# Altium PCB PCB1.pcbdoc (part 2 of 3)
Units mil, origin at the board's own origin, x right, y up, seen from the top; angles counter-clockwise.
Board outline 5971.11 x 4241.46 mil, 4 copper layers (Top Layer, Inner1, Inner2, Bottom Layer); 197 components, 112 nets, 603 pads, 396 vias.
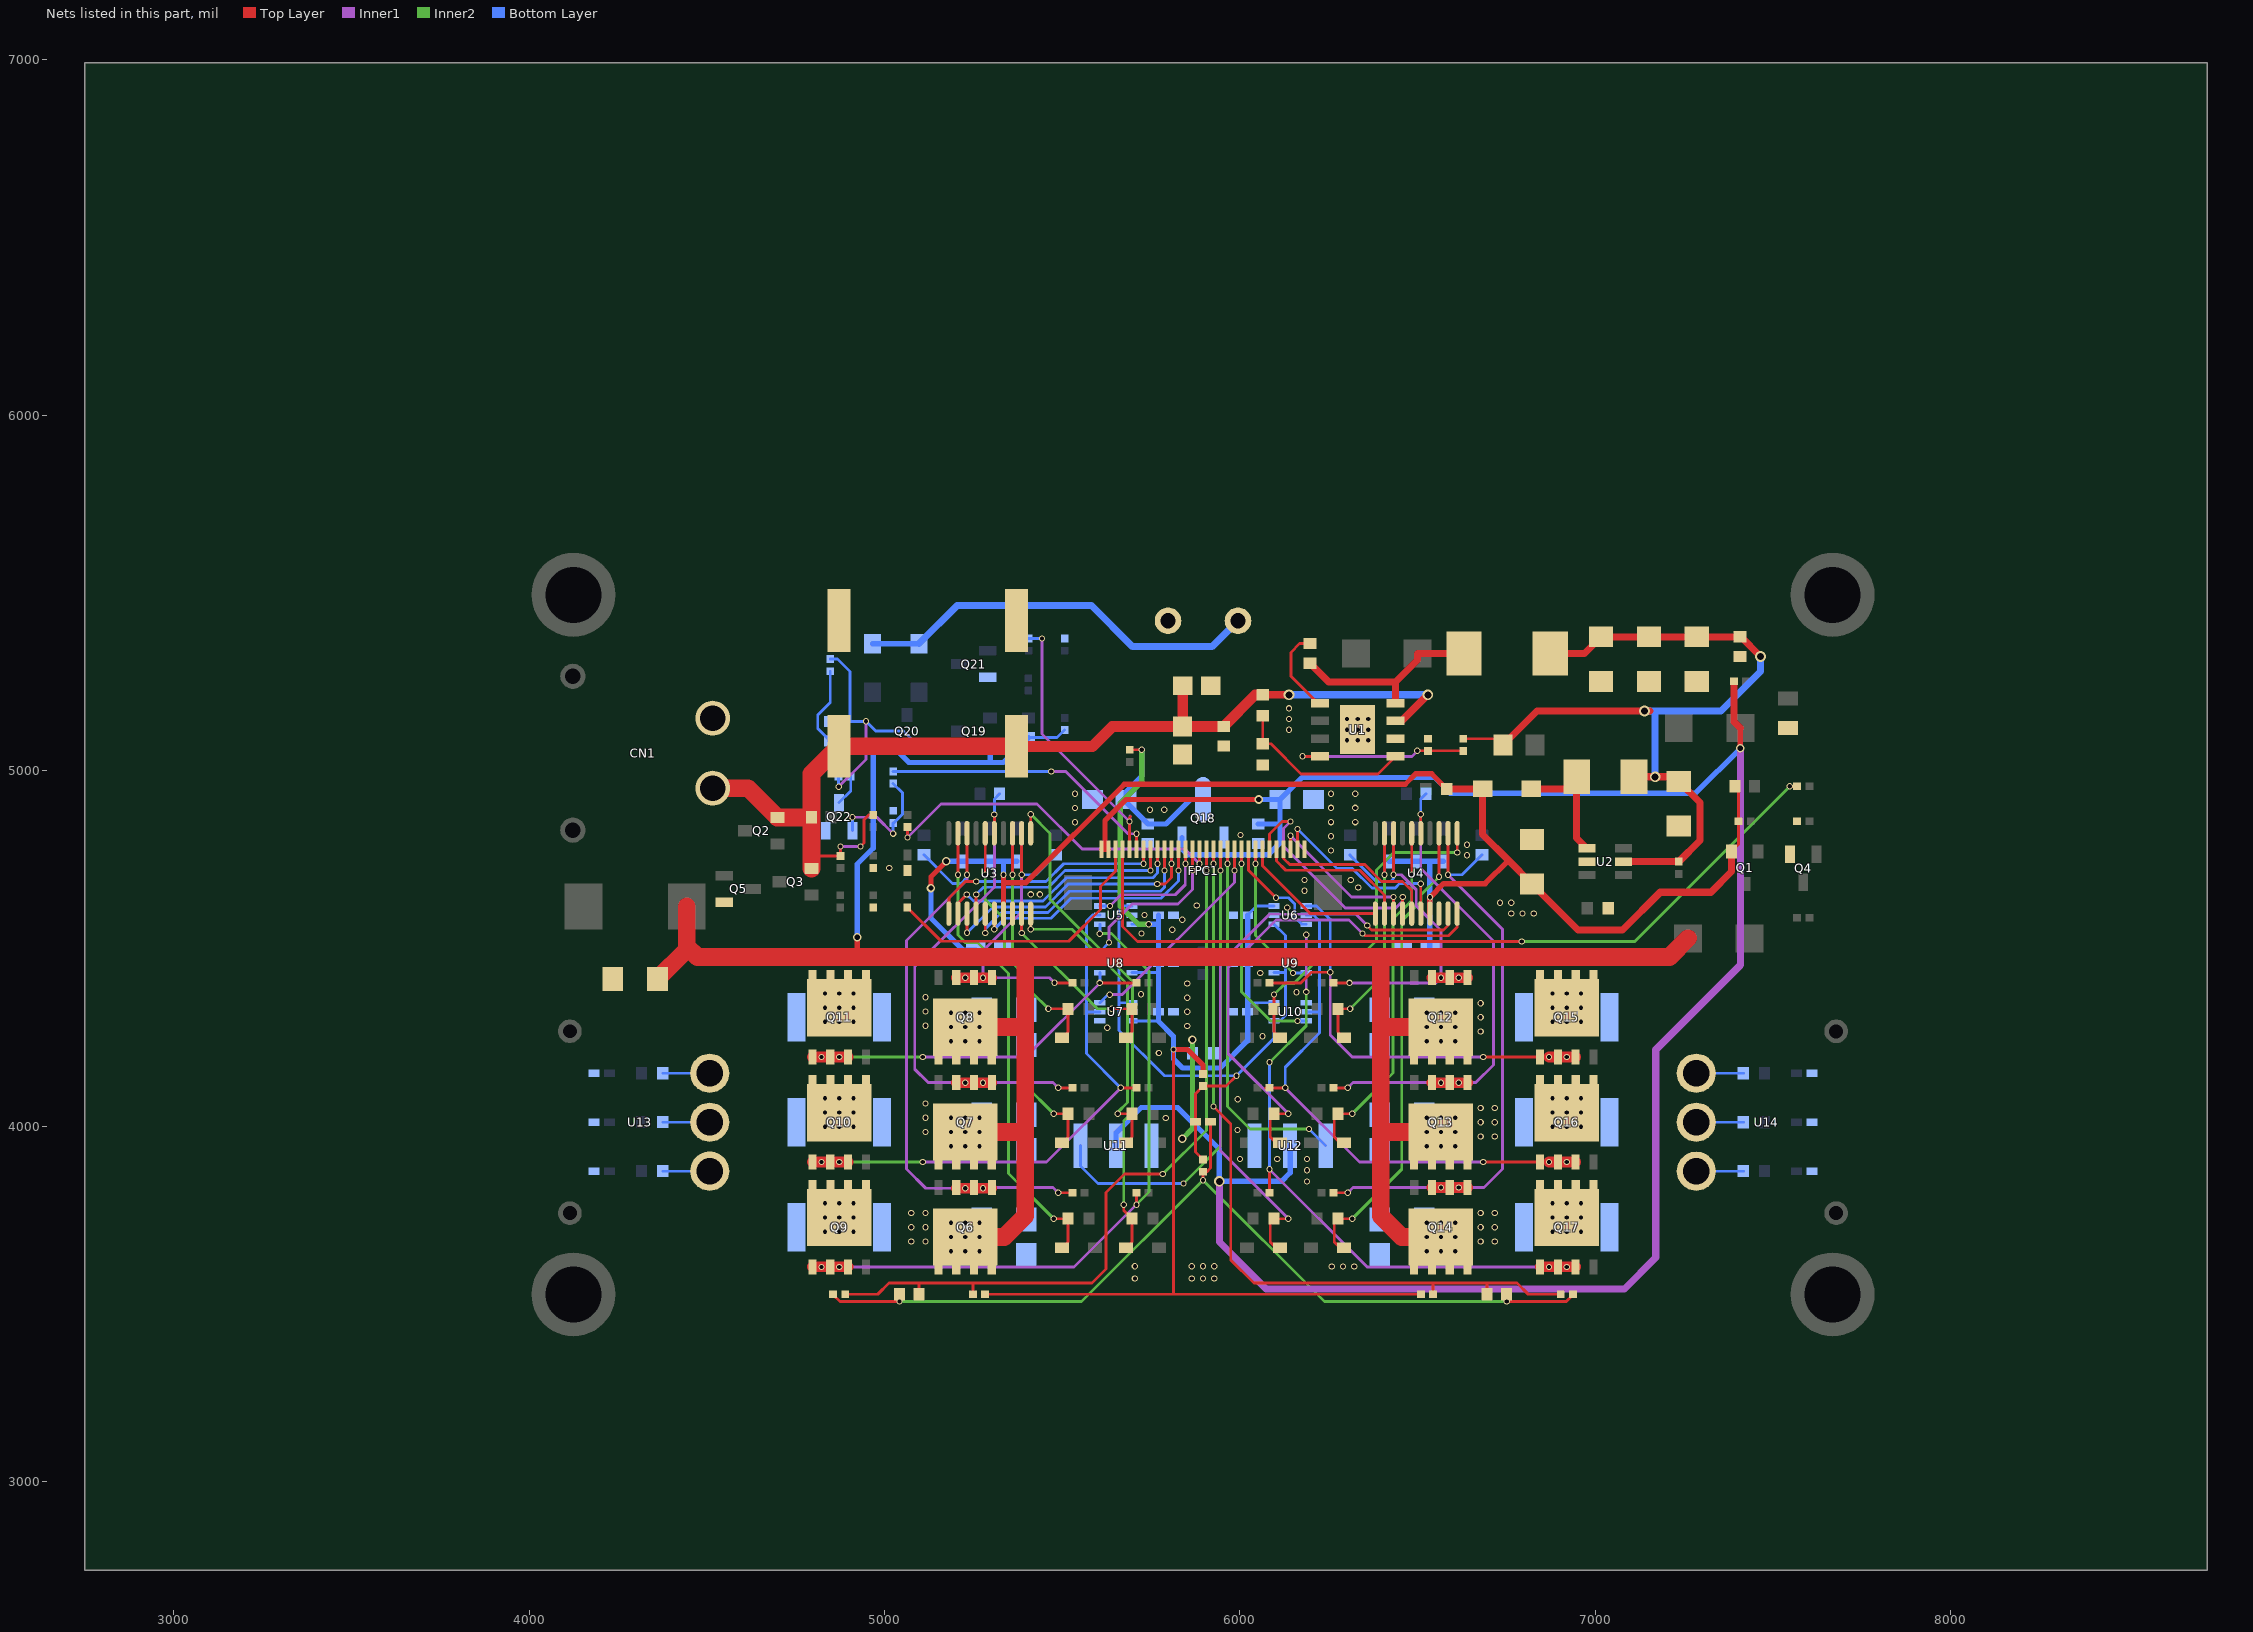
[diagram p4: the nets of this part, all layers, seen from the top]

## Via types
v1: diameter 17.7, hole 12, Top Layer to Bottom Layer, 383 vias
v2: diameter 24, hole 15, Top Layer to Bottom Layer, 7 vias
v3: diameter 30, hole 19.7, Top Layer to Bottom Layer, 6 vias

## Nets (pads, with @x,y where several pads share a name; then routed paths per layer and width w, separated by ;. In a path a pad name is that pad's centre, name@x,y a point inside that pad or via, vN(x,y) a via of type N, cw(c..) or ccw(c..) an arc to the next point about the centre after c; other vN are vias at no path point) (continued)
$1N126462: Q22.1 R78.1 R79.1 | length 334.5
  Inner1 w8: v1(4909.41,4868.96) 4978.03,4868.96 v1(5024.01,4822.99)
  Bottom Layer w8: Q22.1@4909.41,4831.59 v1(4909.41,4868.96) ; v1(5024.01,4822.99) R79.1@5024.01,4853.23 5025.83,4853.23 5049.98,4877.38 5049.98,4937.95 R78.1@5024.01,4963.92
$1N126467: C61.1 Q20.1 R73.1 R75.2 | length 738.7
  Inner1 w8: v1(4870.79,4954.77) 4947.98,5031.96 v1(4947.98,5138.96)
  Bottom Layer w8: C61.1@4847.11,5138.52 4902.68,5138.52 ; R73.1@4847.11,5314 4867.94,5314 4902.68,5279.26 4902.68,5138.52 ; v1(4870.79,4954.77) R75.2@4870.79,4982.68 ; Q20.1@5100.5,5065.69 5099.26,5065.69 5052.98,5111.96 4974.98,5111.96 v1(4947.98,5138.96) 4947.54,5138.52 4902.68,5138.52
$1N126474: Q22.3 R75.1 | length 86
  Bottom Layer w8: Q22.3@4872.01,4910.33 4904.87,4943.19 R75.1@4904.87,4982.68
$1N126564: D24.1 D25.1 U15.1 | length 1151.1
  Bottom Layer w15: D25.1@4966.01,5357.58 D24.1@5097.01,5357.58
  Bottom Layer w20: D24.1@5097.01,5357.58 5204.39,5464.96 5581.98,5464.96 5697.98,5348.96 5921.53,5348.96 U15.1@5994.43,5421.87
$1N167795: R2.1 R9.2 U1.5 | length 507.7
  Top Layer w8: R2.1@6064.01,5154.24 R9.2@6064.01,5075.62 6087.27,5075.62 6171.88,4991.01 6388.24,4991.01 U1.5@6437.56,5040.34
$1N168255: C3.1 U1.1 | length 244.2
  Top Layer w8: C3.1@6197.01,5357.52 6167.64,5357.52 6143.18,5333.06 6143.18,5265.96 6218.81,5190.34 U1.1@6224.97,5190.34
$1N168264: C3.2 L1.1 U1.8 | length 558.4
  Top Layer w20: C3.2@6197.01,5302.4 6249.8,5249.61 6437.56,5249.61 ; U1.8@6437.56,5190.34 6437.56,5249.61 ; L1.1@6630.31,5329.96 6499.62,5329.96 6499.62,5311.67 6437.56,5249.61
$1N168458: R3.1 R10.2 U1.4 | length 507.8
  Top Layer w8: v1(6175.98,5040.34) U1.4@6224.97,5040.34 ; v1(6499.02,5055.92) R10.2@6529.01,5055.92 R3.1@6627.82,5055.92
  Inner1 w8: v1(6175.98,5040.34) 6484.35,5040.34 6499.02,5055 v1(6499.02,5055.92)
$1N213205: D2.2 L2.2 U2.1 | length 355.9
  Top Layer w20: D2.2@6819.32,4948.96 6913.3,4948.96 L2.2@6947.3,4982.96 6947.3,4810.88 U2.1@6976.81,4781.36
+3.3V: C47.2 C48.2 C49.2 C53.2 C54.2 C55.2 C58.1 C59.2 Q18.2 R64.2 R65.2 R66.1 R71.2 U5.3 U6.3 U7.3 U8.3 U9.3 U10.3 | length 4559.5
  Top Layer w8: R64.2@5283.12,3526.84 5812.88,3526.84 ; R71.2@5690.01,5059 v1(5723.84,5059) ; v1(5812.88,4215.76) 5812.88,3526.84 ; R65.2@6508.84,3526.84 5812.88,3526.84
  Top Layer w15: v1(5812.88,4215.76) 5852.18,4215.76 5895.98,4171.96 R66.1@5895.98,4146.7
  Inner2 w15: v1(5723.84,5059) 5723.84,4969.12 5663.48,4908.76 5663.48,4618.36 5713.7,4568.14 v1(5743.13,4568.14)
  Bottom Layer w8: U7.3@5696.28,4295.91 5769.58,4295.91 ; U8.3@5696.28,4432.02 5770.52,4432.02 ; U5.3@5696.28,4568.14 v1(5743.13,4568.14) ; 5770.15,4568.14 5770.52,4568.51 ; 6021.44,4347.11 U10.3@6095.68,4347.11 ; 6021.44,4483.23 U9.3@6095.68,4483.23 ; C55.2@6021.44,4593.76 6047.02,4619.34 U6.3@6095.68,4619.34
  Bottom Layer w15: v1(5723.84,5059) 5723.84,4984.92 5679.22,4940.3 C58.1@5679.22,4918.96 5679.22,4911.78 C59.2@5740.98,4850.02 5792.04,4850.02 5860.98,4918.96 Q18.2@5896.01,4918.96 ; v1(5743.13,4568.14) 5770.15,4568.14 ; C49.2@5770.52,4593.76 5770.52,4568.51 C48.2@5770.52,4457.66 5770.52,4432.02 C47.2@5770.52,4321.46 5770.52,4294.97 5812.88,4252.61 v1(5812.88,4215.76) 5812.88,4188.86 5838.08,4163.66 5944.58,4163.66 6021.44,4240.52 C53.2@6021.44,4321.46 6021.44,4347.11 C54.2@6021.44,4457.66 6021.44,4483.23 C55.2@6021.44,4593.76
+5.8V: C5.2 C6.2 C7.2 C8.2 C9.1 F1.1 L1.2 L2.1 R3.2 R11.2 U2.5 | length 2368.1
  Top Layer w8: R3.2@6627.82,5090 6721.96,5090 F1.1@6740,5071.96
  Top Layer w20: F1.1@6740,5071.96 6836,5167.96 v3@7152.98,5167.96 ; L1.2@6872.71,5329.96 6969.31,5329.96 C6.2@7016.01,5376.66 C7.2@7150.69,5376.66 C8.2@7285.38,5376.66 C9.1@7407.01,5376.66 7409.66,5376.66 v3(7464.78,5321.54) ; U2.5@7079.17,4743.96 R11.2@7234.57,4743.98 ; L2.1@7108.72,4982.96 v3(7168.21,4982.96) 7221.26,4982.96 C5.2@7234.57,4969.66 7293.98,4910.25 7293.98,4803.4 R11.2@7234.57,4743.98
  Bottom Layer w20: v3(7138.21,5167.96) 7168.21,5167.96 ; v3(7168.21,4982.96) 7168.21,5167.96 ; v3(7464.78,5321.54) 7464.78,5279.54 7353.21,5167.96 7168.21,5167.96
+5V: C56.1 C57.2 FPC1.1 FPC1.2 Q18.3 R70.2 U11.2 U12.2 | length 6520.5
  Top Layer w15: FPC1.1@5610.55,4778.4 5620.12,4778.4 ; FPC1.2@5630.23,4778.4 5620.12,4778.4 ; v2(6053.18,4918.96) 5678.98,4918.96 5620.12,4860.1 5620.12,4778.4 ; v2(7407.78,5062.96) 7407.79,5119.96
  Top Layer w20: R70.2@7389.97,5251.26 7389.97,5137.78 7407.79,5119.96
  Inner1 w20: v3(5941.98,3844.46) 5941.98,3673.96 6073.98,3541.96 7081.98,3541.96 7169.98,3629.96 7169.98,4214.96 7407.78,4452.76 v2(7407.78,5062.96)
  Bottom Layer w15: U11.2@5650.98,3944.96 5650.98,3980.96 5722.23,4052.21 5824.73,4052.21 5941.98,3934.96 v3(5941.98,3844.46) 6116.78,3844.46 6140.98,3868.66 U12.2@6140.98,3944.96 ; Q18.3@5836.95,4812.17 5836.95,4778.92 5851.95,4763.92 6080.66,4763.92 6112.74,4796.01 6112.74,4850.02 ; C57.2@6050.98,4850.02 6112.74,4850.02 ; v2(6053.18,4918.96) C56.1@6112.74,4918.96 ; v2(7407.78,5062.96) 7281.78,4936.96 6591.98,4936.96 6547.98,4980.96 6174.74,4980.96 C56.1@6112.74,4918.96 ; 6112.74,4850.02 C56.1@6112.74,4918.96
+12V: C13.2 C14.2 C31.2 C46.2 D2.1 D6.2 D7.2 D8.2 D15.2 D16.2 D17.2 Q1.2 R4.2 R6.2 U3.7 U4.7 | length 4152.9
  Top Layer w8: Q1.2@7382.82,4771.99 7403.19,4792.35 R6.2@7403.19,4857.68 7403.19,4946.12 C14.2@7392.67,4956.63
  Top Layer w15: v2(5130.38,4669.76) 5130.38,4701.63 v2(5173.55,4744.8) ; U3.7@5334.4,4597.93 5334.39,4685.01 ; v1(5334.39,4707.36) 5334.39,4685.01 ; U4.7@6534.4,4597.93 v1(6534.39,4643.6) 6572.86,4682.06 6689.68,4682.06 6755.43,4747.81 ; R4.2@6581.64,4948.96 6539.64,4990.96 6493.98,4990.96 6464.98,4961.96 5674.59,4961.96 5397.64,4685.01 5334.39,4685.01
  Top Layer w20: R4.2@6581.64,4948.96 D2.1@6682.7,4948.96 ; D2.1@6682.7,4945.95 6682.7,4820.55 6755.43,4747.81 C13.2@6821.98,4681.26 6951.18,4552.06 7076.58,4552.06 7182.58,4658.06 7324.93,4658.06 7382.82,4715.95 Q1.2@7382.82,4771.99
  Top Layer w30: D2.1@6682.7,4945.95 D2.1@6682.7,4948.96
  Bottom Layer w15: v2(5130.38,4669.76) 5130.38,4584.86 5220.28,4494.96 C31.2@5256.61,4494.96 ; v2(5173.55,4744.8) D8.2@5220.01,4744.8 D7.2@5295.98,4744.8 5334.39,4744.8 ; v1(5334.39,4707.36) 5334.39,4744.8 ; D6.2@5372.01,4744.8 5334.39,4744.8 ; D17.2@6419.98,4744.8 D16.2@6495.98,4744.8 6535.98,4744.8 ; C46.2@6535.35,4494.96 6534.39,4495.92 v1(6534.39,4643.6) 6534.39,4743.21 6535.98,4744.8 ; D15.2@6571.98,4744.8 6535.98,4744.8
DGND: C47.1 C48.1 C49.1 C50.1 C51.1 C52.1 C53.1 C54.1 C55.1 C56.2 C57.1 C58.2 C59.1 FPC1.30 Q18.1 R15.1 R67.2 R68.1 R69.1 U5.2 U6.2 U7.2 U8.2 U9.2 U10.2 | length 2604.2
  Top Layer w8: R68.1@4855.34,3526.84 4855.34,3525.01 4874.15,3506.21 v1(5041.69,3506.21) C50.1@5041.69,3526.84 ; v1(5895.98,3847.66) R67.2@5895.98,3871.62 5907.3,3871.62 5917.44,3881.77 C52.1@5917.44,4011.66 ; v1(6750.27,3506.21) 6917.82,3506.21 6936.62,3525.01 R69.1@6936.62,3526.84 ; v1(6750.27,3506.21) C51.1@6750.29,3526.86
  Inner2 w8: v1(5041.69,3506.21) 5554.53,3506.21 v1(5895.98,3847.66) 6237.44,3506.21 v1(6750.27,3506.21)
  other v1: 5790.98,4022.96 5993.38,4075.26 5771.83,4205.92 6063.37,4252.81 5851.98,4281.46 5851.98,4321.46 5851.98,4361.46 5721.65,4370.63 5851.98,4401.46 6057.35,4431.02 5722.98,4541.96 5809.41,4552.39 5837.7,4580.68 5731.28,4593.74 6132.87,4614.76 5877.98,4620.96 6255.98,4775.35 6255.98,4815.35 6001.65,4818.86 5535.98,4854.96 6255.98,4855.35 5746.98,4890.06 5786.98,4890.06 5535.98,4894.96 6255.98,4895.35 5535.98,4934.96 6255.98,4935.35
M0_ADC: FPC1.20 U7.6 | length 611.7
  Top Layer w8: v1(5984.56,4718.96) FPC1.20@5984.56,4778.4
  Inner1 w8: v1(5633.53,4369.86) 5668.54,4369.86 5984.56,4685.89 v1(5984.56,4718.96)
  Bottom Layer w8: U7.6@5605.68,4347.11 5628.44,4369.86 v1(5633.53,4369.86)
M0_ADC_A: FPC1.13 U5.6 | length 364.6
  Top Layer w8: v1(5846.77,4737.96) FPC1.13@5846.77,4778.4
  Inner1 w8: v1(5633.98,4619.34) 5665.6,4650.96 5817.78,4650.96 5845.93,4679.11 5845.93,4737.12 v1(5846.77,4737.96)
  Bottom Layer w8: U5.6@5605.68,4619.34 v1(5633.98,4619.34)
M0_ADC_C: FPC1.14 U8.6 | length 478.5
  Top Layer w8: v1(5866.45,4718.96) FPC1.14@5866.45,4778.4
  Inner1 w8: v1(5631.68,4516.32) 5631.68,4559.56 5696.98,4624.86 5825.48,4624.86 5866.45,4665.83 v1(5866.45,4718.96)
  Bottom Layer w8: U8.6@5605.68,4483.23 5605.68,4490.32 v1(5631.68,4516.32)
M0_BK_OUT: FPC1.5 R76.2 | length 764.7
  Top Layer w8: FPC1.5@5689.29,4778.4 v1(5689.28,4857.16) 5689.28,4868.37 5692.17,4871.26
  Inner1 w8: v1(5442.98,5372.23) 5442.98,5103.46 v1(5689.28,4857.16) 5690.73,4858.61 5690.73,4872.71
  Bottom Layer w8: R76.2@5405.57,5372.23 v1(5442.98,5372.23)
M0_HA: D9.1 R20.1 U3.19 | length 1345
  Top Layer w8: v1(5206.44,4707.36) U3.19@5206.44,4823.99 ; v1(5475.91,3739.49) R20.1@5516.01,3739.49 5516.01,3673.97 D9.1@5499.5,3657.46
  Inner2 w8: v1(5206.44,4707.36) 5206.44,4537.51 5226.98,4516.96 5260.98,4516.96 5348.98,4428.96 5348.98,3866.42 v1(5475.91,3739.49)
M0_HB: D10.1 R21.1 U3.16 | length 998.1
  Top Layer w8: v1(5283.21,4707.36) U3.16@5283.22,4823.99 ; v1(5475.91,4034.69) R21.1@5516.01,4034.69 5516.01,3969.17 D10.1@5499.5,3952.66
  Inner2 w8: v1(5283.21,4707.36) 5283.21,4636.73 5336.98,4582.96 5336.98,4481.96 5393.98,4424.96 5393.98,4116.62 v1(5475.91,4034.69)
M0_HC: D11.1 R22.1 U3.13 | length 679.8
  Top Layer w8: v1(5359.98,4707.36) U3.13@5359.99,4823.99 ; v1(5460.91,4329.99) R22.1@5516.01,4329.99 5516.01,4264.47 D11.1@5499.5,4247.96
  Inner2 w8: v1(5359.98,4707.36) 5359.98,4489.96 5415.98,4433.96 5415.98,4374.92 v1(5460.91,4329.99)
M0_ISENSOR_NA: Q10.1 Q10.2 Q10.3 R34.1 R36.1 R37.1 R41.2 U5.5 U7.5 U8.5 | length 1651.9
  Top Layer w8: v1(5664.48,4107.66) R36.1@5708.63,4107.66
  Top Layer w30: Q10.1@4797.26,3899.11 v1(4822.26,3899.07) Q10.2@4847.26,3899.11 v1(4872.46,3899.07) Q10.3@4897.26,3899.11
  Inner1 w8: v1(5107.28,3899.07) 5455.89,3899.07 v1(5664.48,4107.66)
  Inner2 w8: v1(4872.46,3899.07) v1(5107.28,3899.07)
  Bottom Layer w8: U7.5@5605.68,4321.51 5567.98,4321.51 ; U8.5@5605.68,4457.62 5567.98,4457.62 ; U5.5@5605.68,4593.74 5584.76,4593.74 5567.98,4576.96 5567.98,4457.62 ; v1(5664.48,4107.66) 5567.98,4204.16 5567.98,4321.51 ; 5567.98,4321.51 5567.98,4457.62
M0_ISENSOR_PA: Q9.1 Q9.2 Q9.3 R34.2 R35.1 U5.4 | length 1922.6
  Top Layer w8: v1(5708.58,3779.06) R35.1@5708.63,3812.46
  Top Layer w30: Q9.1@4797.26,3603.86 4822.26,3603.86 Q9.2@4847.26,3603.86 4872.46,3603.86 Q9.3@4897.26,3603.86
  Inner1 w8: v1(4872.46,3603.82) 5533.34,3603.82 v1(5708.58,3779.06)
  Inner2 w8: v1(5605.68,4541.56) 5638.38,4541.56 5744.38,4435.56 5744.38,3814.86 v1(5708.58,3779.06)
  Bottom Layer w8: v1(5605.68,4541.56) U5.4@5605.68,4568.14
  other v1: 4822.26,3603.82
M0_ISENSOR_PC: Q11.1 Q11.2 Q11.3 R37.2 R38.1 U8.4 | length 1051.6
  Top Layer w8: v1(5605.68,4402.96) R38.1@5708.63,4402.96
  Top Layer w30: Q11.1@4797.26,4194.36 4822.26,4194.36 Q11.2@4847.26,4194.36 4872.46,4194.36 Q11.3@4897.26,4194.36
  Inner1 w8: v1(5107.28,4194.32) 5397.05,4194.32 v1(5605.68,4402.96)
  Inner2 w8: v1(4872.46,4194.32) v1(5107.28,4194.32)
  Bottom Layer w8: v1(5605.68,4402.96) U8.4@5605.68,4432.02
  other v1: 4822.26,4194.32
M0_LA: D12.1 R30.1 U3.11 | length 1419.2
  Top Layer w8: U3.11@5411.17,4823.99 v1(5411.17,4877.8) ; v1(5672.91,3779.06) 5672.91,3762.59 R30.1@5696.01,3739.49 5696.01,3673.97 D12.1@5679.5,3657.46
  Inner2 w8: v1(5411.17,4877.8) 5465.84,4823.13 5465.84,4638.31 5697.28,4406.86 5697.28,4038.26 5672.91,4013.89 v1(5672.91,3779.06)
M0_LB: D13.1 R31.1 U3.10 | length 884.6
  Top Layer w8: v1(5411.17,4554.09) U3.10@5411.17,4597.93 ; v1(5655.91,4034.69) R31.1@5696.01,4034.69 5696.01,3969.17 D13.1@5679.5,3952.66
  Inner2 w8: v1(5411.17,4554.09) 5527.75,4554.09 5683.33,4398.51 5683.33,4066.31 5655.91,4038.89 v1(5655.91,4034.69)
M0_LC: D14.1 R33.1 U3.9 | length 542.4
  Top Layer w8: v1(5385.58,4543.09) U3.9@5385.58,4597.93 ; v1(5638.91,4329.99) R33.1@5696.01,4329.99 5696.01,4264.47 D14.1@5679.5,4247.96
  Inner2 w8: v1(5385.58,4543.09) 5598.68,4329.99 v1(5638.91,4329.99)
M0_TIM1_CH1: FPC1.11 U3.3 | length 772.5
  Top Layer w8: v1(5232.03,4544.12) U3.3@5232.03,4597.93 ; v1(5766.98,4680.96) 5788.98,4680.96 5807.4,4699.38 v1(5807.4,4737.96) FPC1.11@5807.4,4778.4
  Bottom Layer w8: v1(5232.03,4544.12) 5304.8,4616.89 5452.54,4616.89 5516.61,4680.96 v1(5766.98,4680.96)
M0_TIM1_CH1N: FPC1.12 U3.6 | length 706.8
  Top Layer w8: v1(5308.78,4554.09) U3.6@5308.81,4597.93 ; v1(5827.08,4718.96) FPC1.12@5827.08,4778.4
  Bottom Layer w8: v1(5308.78,4554.09) 5339.58,4584.89 5468.54,4584.89 5524.61,4640.96 5777.98,4640.96 5827.08,4690.06 v1(5827.08,4718.96)
M0_TIM1_CH2: FPC1.9 U3.2 | length 708
  Top Layer w8: U3.2@5206.44,4597.93 5206.44,4627.2 v1(5230.98,4651.74) ; v1(5768.03,4737.96) FPC1.9@5768.03,4778.4
  Bottom Layer w8: v1(5230.98,4651.74) 5249.83,4632.89 5445.91,4632.89 5511.98,4698.96 5755,4698.96 5768.03,4711.99 v1(5768.03,4737.96)
M0_TIM1_CH2N: FPC1.10 U3.5 | length 726.1
  Top Layer w8: v1(5283.22,4543.12) U3.5@5283.22,4597.93 ; v1(5787.71,4718.96) FPC1.10@5787.71,4778.4
  Bottom Layer w8: v1(5283.22,4543.12) 5283.22,4555.2 5328.91,4600.89 5459.91,4600.89 5519.98,4660.96 5776.56,4660.96 5787.71,4672.11 v1(5787.71,4718.96)
M0_TIM1_CH3: FPC1.7 U3.1 | length 672
  Top Layer w8: U3.1@5180.85,4597.93 5180.85,4641.83 5227.06,4688.04 v1(5257.62,4688.04) ; v1(5728.66,4737.96) FPC1.7@5728.66,4778.4
  Bottom Layer w8: v1(5257.62,4688.04) 5454.25,4688.04 5504.17,4737.96 v1(5728.66,4737.96)
M0_TIM1_CH3N: FPC1.8 U3.4 | length 631.8
  Top Layer w8: U3.4@5257.62,4597.93 v1(5257.62,4651.74) ; v1(5748.34,4718.96) FPC1.8@5748.34,4778.4
  Bottom Layer w8: v1(5257.62,4651.74) 5277.92,4672.04 5460.88,4672.04 5507.8,4718.96 v1(5748.34,4718.96)
M0_U: C28.2 Q6.1 Q6.2 Q6.3 Q9.5 Q9.6 Q9.7 Q9.8 Q9.9 R23.1 R24.2 U3.18 U13.3 | length 1848.2
  Top Layer w8: v1(5232.03,4707.36) U3.18@5232.03,4822.85 ; v1(5488.53,3812.46) R23.1@5528.63,3812.46
  Top Layer w30: Q6.3@5201.79,3825.12 v1(5226.79,3825.09) v1(5276.99,3825.09) Q6.1@5301.79,3825.09
  Inner1 w8: v1(5226.79,3825.09) 5115.86,3825.09 5061.98,3878.96 5061.98,4521.96 5232.03,4692.01 v1(5232.03,4707.36) ; 5288.9,3827.02 5473.97,3827.02 v1(5488.53,3812.46)
  Bottom Layer w8: R24.2@4375.64,3873.16 U13.3@4507.93,3873.17 ; C28.2@5110.98,4763.4 5191.3,4683.08 5215.1,4683.08 5232.03,4700.01 v1(5232.03,4707.36)
  other v1: 4832.26,3702.82 4872.26,3702.82 4912.26,3702.82 4832.26,3742.82 4872.26,3742.82 4912.26,3742.82 4832.26,3782.82 4872.26,3782.82 4912.26,3782.82
M0_V: C27.2 Q7.1 Q7.2 Q7.3 Q10.5 Q10.6 Q10.7 Q10.8 Q10.9 R25.1 R26.2 U3.15 U13.2 | length 1625.1
  Top Layer w8: U3.15@5308.81,4823.99 v1(5308.81,4876.66) ; v1(5488.53,4107.66) R25.1@5528.63,4107.66
  Top Layer w30: Q7.3@5201.77,4122.22 v1(5226.77,4122.19) 5238.68,4122.22 ; Q7.1@5301.77,4122.19 v1(5276.97,4122.19) 5251.77,4122.22 5238.68,4122.22 ; Q7.1@5301.79,4122.26 5276.97,4122.26 Q7.2@5251.79,4122.26 5238.68,4122.22
  Inner1 w8: v1(5226.77,4122.19) 5122.72,4122.22 5084.98,4159.96 5084.98,4448.96 5308.81,4672.79 v1(5308.81,4876.66) ; 5288.88,4122.22 5473.97,4122.22 v1(5488.53,4107.66)
  Bottom Layer w8: R26.2@4375.64,4010.96 U13.2@4507.93,4010.96 ; v1(5308.81,4876.66) 5308.81,4920.23 C27.2@5323.54,4934.96
  other v1: 4832.26,3998.07 4872.26,3998.07 4912.26,3998.07 4832.26,4038.07 4872.26,4038.07 4912.26,4038.07 4832.26,4078.07 4872.26,4078.07 4912.26,4078.07
M0_W: C23.2 Q8.1 Q8.2 Q8.3 Q11.5 Q11.6 Q11.7 Q11.8 Q11.9 R27.1 R28.2 U3.12 U13.1 | length 1050.7
  Top Layer w8: v1(5385.58,4707.36) U3.12@5385.58,4822.85 ; 5486.78,4402.96 R27.1@5528.63,4402.96
  Top Layer w30: Q8.3@5201.79,4417.56 5226.79,4417.58 Q8.2@5251.79,4417.56 v1@5276.99,4417.58 ; v1(5276.99,4417.54) Q8.1@5301.79,4417.54
  Inner1 w8: v1(5385.58,4707.36) 5385.58,4602.06 5276.99,4493.47 v1(5276.99,4417.54) 5463.89,4417.54 v1(5477.82,4403.61)
  Bottom Layer w8: R28.2@4375.64,4148.76 U13.1@4507.93,4148.75 ; v1(5385.58,4707.36) 5425.97,4707.36 C23.2@5482.01,4763.4
  other v1: 4832.26,4293.28 4872.26,4293.28 4912.26,4293.28 4832.26,4333.28 4872.26,4333.28 4912.26,4333.28 4832.26,4373.28 4872.26,4373.28 4912.26,4373.28 5226.79,4417.54
M1_ADC: FPC1.21 U10.6 | length 616.4
  Top Layer w8: v1(6004.25,4737.96) FPC1.21@6004.25,4778.4
  Inner2 w8: v1(6004.25,4737.96) 6004.25,4378.09 6086.44,4295.91 v1(6162.04,4295.91)
  Bottom Layer w8: v1(6162.04,4295.91) U10.6@6186.28,4295.91
M1_ADC_A: FPC1.22 U6.6 | length 305.2
  Top Layer w8: FPC1.22@6023.93,4778.4 6023.93,4719.85 v1(6101.11,4642.67)
  Bottom Layer w8: v1(6101.11,4642.67) 6136.27,4642.67 6153.98,4624.96 6153.98,4588.3 6174.14,4568.14 U6.6@6186.28,4568.14
M1_ADC_C: FPC1.23 U9.6 | length 428.8
  Top Layer w8: v1(6043.62,4737.96) FPC1.23@6043.62,4778.4
  Inner2 w8: v1(6043.62,4737.96) 6043.62,4536.32 v1(6148.98,4430.96)
  Bottom Layer w8: v1(6148.98,4430.96) 6185.22,4430.96 U9.6@6186.28,4432.02
M1_BK_OUT: FPC1.6 R78.2 | length 801.8
  Top Layer w8: FPC1.6@5708.97,4778.4 v1(5708.97,4822.63)
  Inner1 w8: v1(5468.98,4997.96) 5509.68,4997.96 5685.02,4822.63 v1(5708.97,4822.63)
  Bottom Layer w8: R78.2@5024.01,4998 v1@5468.94,4998
M1_HA: D18.1 R42.1 U4.19 | length 656.8
  Top Layer w8: D18.1@6292.45,4247.96 6275.94,4264.47 R42.1@6275.94,4329.99 v1@6309.85,4329.99 ; v1(6406.44,4707.36) U4.19@6406.44,4823.99
  Inner2 w8: v1(6309.87,4329.96) 6406.44,4426.53 v1(6406.44,4707.36)
M1_HB: D19.1 R43.1 U4.16 | length 987.5
  Top Layer w8: R43.1@6265.33,4034.69 6265.33,3969.17 D19.1@6281.83,3952.66 ; R43.1@6275.94,4034.69 v1(6316.04,4034.69) ; v1(6483.22,4707.36) U4.16@6483.22,4823.99
  Inner2 w8: v1(6316.04,4034.69) 6430.98,4149.64 6430.98,4582.96 6483.22,4635.2 v1(6483.22,4707.36)
M1_HC: D20.1 R44.1 U4.13 | length 1318.3
  Top Layer w8: D20.1@6281.83,3657.46 6265.33,3673.97 6265.33,3728.87 R44.1@6275.94,3739.49 v1(6316.04,3739.49) ; v1@6559.99,4701.93 U4.13@6559.99,4823.99
  Inner2 w8: v1(6316.04,3739.49) 6454.98,3878.44 6454.98,4577.96 6509.98,4632.96 6509.98,4651.36 v1(6559.99,4701.36)
M1_ISENSOR_NA: Q16.1 Q16.2 Q16.3 R56.1 R58.1 R59.1 R63.2 U6.5 U9.5 U10.5 | length 1587.5
  Top Layer w8: R58.1@6072.72,4107.66 v1(6127.48,4107.66) ; v1(6684.68,3899.07) Q16.1@6844.51,3899.11 v1(6869.51,3899.07)
  Top Layer w30: v1(6869.51,3899.07) Q16.2@6894.51,3899.11 v1(6919.71,3899.07) Q16.3@6944.51,3899.11
  Inner1 w8: v1(6127.48,4107.66) 6336.07,3899.07 v1(6684.68,3899.07)
  Bottom Layer w8: v1(6127.48,4107.66) 6127.48,4165.46 6223.98,4261.96 6223.98,4321.51 ; U10.5@6186.28,4321.51 6223.98,4321.51 ; U9.5@6186.28,4457.62 6223.98,4457.62 ; U6.5@6186.28,4593.74 6207.2,4593.74 6223.98,4576.96 6223.98,4457.62 ; 6223.98,4321.51 6223.98,4457.62
M1_ISENSOR_PA: Q15.1 Q15.2 Q15.3 R56.2 R57.1 U6.4 | length 1307.6
  Top Layer w8: R57.1@6083.32,4402.96 6170.98,4402.96 6200.82,4432.8 v1(6253.98,4432.8) ; v1(6684.7,4194.35) 6844.51,4194.35 v1(6869.51,4194.35)
  Top Layer w30: v1@6869.51,4194.39 Q15.2@6894.51,4194.39 6919.71,4194.39 Q15.3@6944.51,4194.39
  Inner1 w8: v1(6253.98,4432.8) 6253.98,4256.1 6315.74,4194.35 v1(6684.7,4194.35)
  Bottom Layer w8: U6.4@6186.28,4619.34 6215.6,4619.34 6253.98,4580.96 v1(6253.98,4432.8)
  other v1: 6919.71,4194.35
M1_ISENSOR_PC: Q17.1 Q17.2 Q17.3 R59.2 R60.1 U9.4 | length 1821.4
  Top Layer w8: R60.1@6083.32,3812.46 v1@6083.32,3878.22
  Top Layer w30: Q17.1@6844.51,3603.84 v1(6869.51,3603.8) Q17.2@6894.51,3603.84 v1(6919.71,3603.8) Q17.3@6944.51,3603.84
  Inner1 w8: v1(6083.28,3878.26) 6083.52,3878.26 6357.99,3603.8 v1(6869.51,3603.8) ; v1@6186.28,4379.94 v1(6186.28,4538.44)
  Inner2 w8: v1(6083.28,4179.4) 6186.28,4282.4 v1(6186.28,4377.63)
  Bottom Layer w8: v1(6083.28,3878.26) v1(6083.28,4179.4) ; U9.4@6186.28,4483.23 v1(6186.28,4538.44)
M1_LA: D21.1 R52.1 U4.11 | length 980.1
  Top Layer w8: v1(6095.94,4370.09) R52.1@6095.94,4329.99 6095.94,4264.47 D21.1@6112.45,4247.96 ; v1(6611.16,4769.63) U4.11@6611.16,4823.44
  Inner2 w8: v1(6095.94,4370.09) 6128.82,4402.96 6152.83,4402.96 6235.83,4485.96 6347.98,4485.96 6383.98,4521.96 6383.98,4720.96 6432.65,4769.63 v1(6611.16,4769.63)
M1_LB: D22.1 R53.1 U4.10 | length 1376.2
  Top Layer w8: R53.1@6085.33,4034.69 6085.33,3969.17 D22.1@6101.83,3952.66 ; R53.1@6095.94,4034.69 v1(6136.04,4034.69) ; v1(6344.98,4541.96) 6351.3,4535.64 6586.66,4535.64 6611.17,4560.15 U4.10@6611.17,4597.93
  Inner1 w8: v1(6136.04,4034.69) 5966.98,4203.75 5966.98,4445.96 6100.98,4579.96 6306.98,4579.96 v1(6344.98,4541.96)
M1_LC: D23.1 R55.1 U4.9 | length 1686.3
  Top Layer w8: D23.1@6101.83,3657.46 6085.33,3673.97 6085.33,3728.87 R55.1@6095.94,3739.49 v1(6136.04,3739.49) ; v1(6357.98,4564.16) 6370.5,4551.64 6572.66,4551.64 6585.58,4564.56 U4.9@6585.58,4597.93
  Inner1 w8: v1(6136.04,3739.49) 5944.36,3931.17 5944.36,4457.34 6082.98,4595.96 6326.18,4595.96 v1(6357.98,4564.16)
M1_TIM8_CH1: FPC1.28 U4.3 | length 446.5
  Top Layer w8: FPC1.28@6142.04,4778.4 v1(6142.04,4816.83) ; U4.3@6432.03,4597.93 v1(6432.03,4644.74)
  Inner1 w8: v1(6142.04,4816.83) 6314.13,4644.74 v1(6432.03,4644.74)
M1_TIM8_CH1N: FPC1.29 U4.6 | length 562.5
  Top Layer w8: FPC1.29@6161.73,4778.4 v1(6161.73,4835.83) ; U4.6@6508.81,4597.93 v1(6508.81,4682.14)
  Bottom Layer w8: v1(6161.73,4835.83) 6272.6,4724.96 6315.98,4724.96 6370.98,4669.96 6436.98,4669.96 6449.16,4682.14 v1(6508.81,4682.14)
M1_TIM8_CH2: FPC1.26 U4.2 | length 428.1
  Top Layer w8: FPC1.26@6102.67,4778.4 6102.67,4746.27 6128.98,4719.96 6336.98,4719.96 6406.44,4650.51 U4.2@6406.44,4597.93
M1_TIM8_CH2N: FPC1.27 U4.5 | length 488.2
  Top Layer w8: FPC1.27@6122.36,4778.4 6122.36,4753.42 6139.82,4735.96 6351.18,4735.96 6398.63,4688.51 6457.43,4688.51 6483.22,4662.73 U4.5@6483.22,4597.93
M1_TIM8_CH3: FPC1.24 U4.1 | length 419.3
  Top Layer w8: FPC1.24@6063.3,4778.4 6063.3,4732.34 6197.71,4597.93 U4.1@6380.85,4597.93
M1_TIM8_CH3N: FPC1.25 U4.4 | length 666.7
  Top Layer w8: FPC1.25@6082.99,4778.4 6082.99,4822.17 6117.94,4857.12 v1@6140.75,4857.12 ; U4.4@6457.62,4597.93 v1(6457.62,4644.74)
  Inner1 w8: v1(6142.04,4857.12) 6122.68,4837.76 6122.68,4787.46 6296.18,4613.96 6438.15,4613.96 6457.62,4633.43 v1(6457.62,4644.74)
M1_U: C43.2 Q12.1 Q12.2 Q12.3 Q15.5 Q15.6 Q15.7 Q15.8 Q15.9 R45.1 R46.2 U4.18 U14.3 | length 1192.5
  Top Layer w8: R45.1@6263.32,4402.96 v1@6305.18,4402.96 ; v1(6432.03,4707.36) U4.18@6432.03,4823.99
  Top Layer w30: Q12.3@6540.37,4417.56 6565.37,4417.56 Q12.2@6590.37,4417.56 6615.57,4417.56 6628.26,4417.56 ; v1(6615.57,4417.52) Q12.1@6640.37,4417.52
  Inner1 w8: v1(6308.12,4402.96) 6550.81,4402.96 v1(6565.37,4417.52) 6565.37,4550.57 6495.98,4619.96 6495.98,4664.96 6453.58,4707.36 v1(6432.03,4707.36)
  Bottom Layer w8: C43.2@6310.01,4763.4 6310.01,4761.94 6383.43,4688.51 6424.03,4688.51 6432.03,4696.51 v1(6432.03,4707.36) ; U14.3@7284,4148.74 R46.2@7416.3,4148.74
  other v1: 6879.51,4293.35 6919.51,4293.35 6959.51,4293.35 6879.51,4333.35 6919.51,4333.35 6959.51,4333.35 6879.51,4373.35 6919.51,4373.35 6959.51,4373.35
M1_V: C42.2 Q13.1 Q13.2 Q13.3 Q16.5 Q16.6 Q16.7 Q16.8 Q16.9 R47.1 R48.2 U4.15 U14.2 | length 1578.3
  Top Layer w8: R47.1@6263.62,4107.66 v1(6303.42,4107.66) ; U4.15@6508.81,4823.99 v1(6508.81,4877.8)
  Top Layer w30: Q13.3@6540.37,4122.26 6565.37,4122.26 Q13.2@6590.37,4122.26 6603.48,4122.26 6615.57,4122.26 6628.28,4122.26 ; v1(6615.57,4122.22) Q13.1@6640.37,4122.22
  Inner1 w8: v1(6303.42,4107.66) 6317.98,4122.22 v1(6565.37,4122.22) ; v1(6508.81,4877.8) 6508.81,4725.13 6712.98,4520.96 6712.98,4171.96 6663.24,4122.22 v1(6615.57,4122.22)
  Bottom Layer w8: v1(6508.81,4877.8) 6508.81,4920.23 C42.2@6523.54,4934.96 ; U14.2@7284,4010.95 R48.2@7416.32,4010.95
  other v1: 6879.51,3998.07 6919.51,3998.07 6959.51,3998.07 6879.51,4038.07 6919.51,4038.07 6959.51,4038.07 6879.51,4078.07 6919.51,4078.07 6959.51,4078.07
M1_W: C38.2 Q14.1 Q14.2 Q14.3 Q17.5 Q17.6 Q17.7 Q17.8 Q17.9 R49.1 R50.2 U4.12 U14.1 | length 1813.1
  Top Layer w8: R49.1@6263.32,3812.46 v1(6303.12,3812.46) ; v1(6585.58,4707.36) U4.12@6585.58,4823.99
  Top Layer w30: Q14.3@6540.37,3827.06 6565.37,3827.06 Q14.2@6590.37,3827.06 6615.57,3827.06 6628.26,3827.06 ; v1(6615.57,3827.02) Q14.1@6640.37,3827.02
  Inner1 w8: v1(6303.12,3812.46) 6317.69,3827.02 6553.26,3827.02 ; v1(6585.58,4707.36) 6738.98,4553.96 6738.98,3878.96 6687.04,3827.02 v1(6615.57,3827.02)
  Bottom Layer w8: v1(6585.58,4707.36) 6624.94,4707.36 C38.2@6680.98,4763.4 ; U14.1@7284,3873.16 R50.2@7416.32,3873.16
  other v1: 6879.51,3702.8 6919.51,3702.8 6959.51,3702.8 6879.51,3742.8 6919.51,3742.8 6959.51,3742.8 6879.51,3782.8 6919.51,3782.8 6959.51,3782.8 6565.37,3827.02
MOTOR_EN1: FPC1.4 R16.2 | length 2314.1
  Top Layer w8: FPC1.4@5669.6,4778.4 5669.6,4561.34 5711.35,4519.6 6599.61,4519.6 ; 6599.98,4519.96 6599.61,4519.6 ; v1(6792.98,4519.56) 6599.61,4519.6 ; v1(7546.98,4955.96) 7567.16,4955.96 R16.2@7567.83,4956.64
  Inner2 w8: v1(6792.98,4519.56) 7110.58,4519.56 v1(7546.98,4955.96)
MOTOR_EN2: FPC1.3 R17.2 | length 806.9
  Top Layer w8: R17.2@5063.96,4615.45 5159.44,4519.96 5518.38,4519.96 5607.58,4609.16 5607.58,4674.56 5649.92,4716.9 FPC1.3@5649.92,4778.4
PGND: C1.2 C2.2 C5.1 C6.1 C7.1 C8.1 C9.2 C10.1 C11.1 C12.1 C13.1 C15.1 C16.1 C17.1 C18.1 C19.1 C20.1 C21.1 C22.1 C24.2 C25.2 C26.2 C31.1 C32.1 C33.1 C34.1 C35.1 C36.1 C37.1 C39.2 C40.2 C41.2 C46.1 CN1.1 LED1.2 Q4.2 Q5.2 Q21.2 Q22.2 R9.1 R10.1 R12.1 R14.2 R15.2 R18.2 R19.2 R41.1 R63.1 R77.2 R79.2 U1.6 U1.9 U2.2 U3.8 U4.8 U7.4 U10.4 U11.1 U12.3 U15.2 | length 329.2
  Inner2 w15: v2(5837.78,3964.46) 5866.32,3993 v2(5866.32,4243.42)
  Bottom Layer w15: R15.2@5866.32,4204.96 v2(5866.32,4243.42)
  other v1: 5704.28,3570.96 5864.28,3570.96 5895.98,3570.96 5927.73,3570.96 6258.03,3605.2 6289.68,3605.2 6321.43,3605.2 5704.28,3605.96 5864.28,3605.96 5895.98,3605.96 5927.73,3605.96 5074.88,3675.46 5114.88,3675.46 6677.08,3675.46 6717.08,3675.46 5074.88,3715.46 5114.88,3715.46 6677.08,3715.46 6717.08,3715.46 5074.88,3755.46 5114.88,3755.46 6677.08,3755.46 6717.08,3755.46 6188.85,3844.21 6188.85,3875.96 5999.78,3907.56 6104.98,3907.71 6188.85,3907.71 6677.08,3970.66 6717.08,3970.66 5114.88,3983.3 5993.08,3988.86 6677.08,4010.66 6717.08,4010.66 5114.88,4023.3 6677.08,4050.66 6717.08,4050.66 5114.88,4063.3 6677.08,4265.96 5626.21,4277.01 5114.88,4282.59 6677.08,4305.96 5114.88,4322.59 6677.08,4345.96 5114.88,4362.59 6158.98,4376.96 6763.18,4598.06 6794.93,4598.06 6826.68,4598.06 6731.43,4628.32 6763.18,4628.32 5411.18,4651.96 5436.98,4651.96 6181.52,4662.57 6332.59,4671.36 6181.52,4692.57 6311.38,4692.57 5013.11,4726.5 6638.98,4761.96 6638.98,4791.96 6324,4855.35 6324,4895.35 6324,4935.35 6301.26,5085.35 6331.27,5085.34 6361.27,5085.34 6137.88,5115.35 6301.26,5115.35 6331.27,5115.34 6361.27,5115.34 6137.88,5145.35 6301.26,5145.35 6331.27,5145.34 6361.27,5145.34 6137.88,5175.35
PVCC: C1.1 C2.1 C4.2 C10.2 C11.2 C12.2 CN1.2 Q2.2 Q3.2 R1.2 R2.2 R5.2 U1.7 | length 2918.6
  Top Layer w8: 4794.15,4759.64 4875.89,4759.64 R1.2@4876.01,4759.76 v1(4876.01,4786.96) ; v1(4931.98,4786.96) 4941.98,4796.96 4941.98,4861.96 4955.42,4875.4 R5.2@4968.11,4875.4
  Top Layer w20: R2.2@6064.01,5213.56 v3(6137.88,5213.56) ; U1.7@6437.56,5140.34 6455.27,5140.34 v3(6528.48,5213.55)
  Top Layer w30: C2.1@5371.01,5068.8 5371.65,5068.16 5584.88,5068.16 5641.05,5124.33 C10.2@5838.01,5124.33 ; C11.2@5838.64,5238.96 5838.64,5124.96 C10.2@5838.01,5124.33 ; C12.2@5953.95,5124.33 C10.2@5838.01,5124.33 ; C12.2@5954.01,5124.39 6043.18,5213.56 R2.2@6064.01,5213.56
  Top Layer w50: CN1.2@4516.48,4950.76 4616.03,4950.76 Q2.2@4698.13,4868.66 C4.2@4794.15,4868.66 ; Q3.2@4794.15,4724.7 4794.15,4759.64 C4.2@4794.15,4868.66 ; C2.1@5371.01,5068.8 C1.1@4871.37,5068.8 4794.15,4991.58 C4.2@4794.15,4868.66
  Inner1 w8: v1(4876.01,4786.96) v1(4931.98,4786.96)
  Bottom Layer w20: v3(6137.88,5213.56) 6525.48,5213.56 v3@6528.48,5210.56
S0_PWM: FPC1.18 U11.3 | length 1350.1
  Top Layer w8: v1(5945.19,4718.96) FPC1.18@5945.19,4778.4
  Inner2 w8: v1(5840.8,3838.71) 5945.19,3943.11 v1(5945.19,4718.96)
  Bottom Layer w8: U11.3@5550.98,3944.96 5550.98,3887.96 5600.23,3838.71 v1(5840.8,3838.71)
S1_PWM: FPC1.19 U12.1 | length 1045
  Top Layer w8: v1(5964.88,4737.96) FPC1.19@5964.88,4778.4
  Inner2 w8: v1(5964.88,4737.96) 5964.88,4055.06 6027.98,3991.96 v1(6193.98,3991.96)
  Bottom Layer w8: v1(6193.98,3991.96) U12.1@6240.98,3944.96
TEMP0_ADC: C50.2 FPC1.16 R64.1 R68.2 | length 2187.5
  Top Layer w8: R68.2@4889.42,3526.84 4980.86,3526.84 5012.74,3558.72 5096.79,3558.72 ; C50.2@5096.79,3526.86 5096.79,3558.72 ; R64.1@5249.04,3526.84 5249.04,3558.72 ; v1(5782.8,3864.96) 5674.98,3864.96 5622.98,3812.96 5622.98,3597.96 5583.74,3558.72 5249.04,3558.72 ; v1(5905.82,4718.96) FPC1.16@5905.82,4778.4 ; 5096.79,3558.72 5249.04,3558.72
  Inner2 w8: v1(5782.8,3864.96) 5905.82,3987.99 v1(5905.82,4718.96)
TEMP1_ADC: C51.2 FPC1.17 R65.1 R69.2 | length 2207
  Top Layer w8: v1(5925.51,4054.96) 5974.23,4006.25 5974.23,3623.71 6039.23,3558.72 6542.92,3558.72 ; v1(5925.51,4737.96) FPC1.17@5925.51,4778.4 ; R65.1@6542.92,3526.84 6542.92,3558.72 ; C51.2@6695.17,3526.86 6695.17,3558.72 ; R69.2@6902.54,3526.84 6811.11,3526.84 6779.23,3558.72 6695.17,3558.72 ; 6542.92,3558.72 6695.17,3558.72
  Inner2 w8: v1(5925.51,4054.96) v1(5925.51,4737.96)
VIN: C16.2 C17.2 C18.2 C19.2 C20.2 C21.2 C22.2 C32.2 C33.2 C34.2 C35.2 C36.2 C37.2 C60.2 C61.2 Q6.5 Q6.6 Q6.7 Q6.8 Q6.9 Q7.5 Q7.6 Q7.7 Q7.8 Q7.9 Q8.5 Q8.6 Q8.7 Q8.8 Q8.9 Q12.5 Q12.6 Q12.7 Q12.8 Q12.9 Q13.5 Q13.6 Q13.7 Q13.8 Q13.9 Q14.5 Q14.6 Q14.7 Q14.8 Q14.9 Q19.2 Q20.2 R72.2 R73.2 | length 6925
  Top Layer w15: 4922.98,4475.91 v2(4922.98,4531.47)
  Top Layer w50: C16.2@4360.72,4413.96 4443.15,4496.39 4443.15,4506.24 ; 4443.15,4617.96 4443.15,4506.24 ; Q6.9@5278.7,3688.1 5336.89,3688.1 5395.98,3747.2 5395.98,3983.3 ; Q7.9@5278.68,3983.3 5395.98,3983.3 ; Q8.9@5278.7,4278.6 5395.98,4278.6 ; Q14.9@6513.26,3688.1 6455.08,3688.1 6395.98,3747.2 6395.98,3983.3 ; Q12.9@6513.26,4278.6 6395.98,4278.6 ; Q13.9@6513.28,3983.3 6395.98,3983.3 ; 7260.86,4528.42 7208.35,4475.91 6395.98,4475.91 ; 4443.15,4506.24 4473.48,4475.91 4922.98,4475.91 5395.98,4475.91 ; 5395.98,3983.3 5395.98,4278.6 ; 5395.98,4278.6 5395.98,4475.91 ; 5395.98,4475.91 6395.98,4475.91 ; 6395.98,3983.3 6395.98,4278.6 ; 6395.98,4278.6 6395.98,4475.91
  Bottom Layer w8: C61.2@4847.11,5083.4 4811.98,5118.53 4811.98,5156.96 4847.11,5192.09 R73.2@4847.11,5279.92 ; C60.2@5404.85,5093.24 5485.53,5093.24 R72.2@5506.57,5114.28
  Bottom Layer w15: C61.2@4847.11,5083.4 4968.11,5083.4 ; v2(4922.98,4531.47) 4922.98,4736.96 4968.11,4782.09 4968.11,5083.4 ; Q19.2@5297.28,5073.56 5297.28,5022.96 ; C60.2@5404.85,5093.24 5334.57,5022.96 5297.28,5022.96 ; 4968.11,5083.4 5007.98,5083.4 Q20.2@5025.69,5065.69 5068.42,5022.96 5297.28,5022.96
  other v1: 5186.79,3648.1 5226.79,3648.1 5266.79,3648.1 6525.37,3648.1 6565.37,3648.1 6605.37,3648.1 5186.79,3688.1 5226.79,3688.1 5266.79,3688.1 6525.37,3688.1 6565.37,3688.1 6605.37,3688.1 5186.79,3728.1 5226.79,3728.1 5266.79,3728.1 6525.37,3728.1 6565.37,3728.1 6605.37,3728.1 5186.79,3943.3 5226.79,3943.3 5266.79,3943.3 6525.37,3943.3 6565.37,3943.3 6605.37,3943.3 5186.79,3983.3 5226.79,3983.3 5266.79,3983.3 6525.37,3983.3 6565.37,3983.3 6605.37,3983.3 5186.79,4023.3 5226.79,4023.3 5266.79,4023.3 6525.37,4023.3 6565.37,4023.3 6605.37,4023.3 5186.79,4238.6 5226.79,4238.6 5266.79,4238.6 6525.37,4238.6 6565.37,4238.6 6605.37,4238.6 5186.79,4278.6 5226.79,4278.6 5266.79,4278.6 6525.37,4278.6 6565.37,4278.6 6605.37,4278.6 5186.79,4318.6 5226.79,4318.6 5266.79,4318.6 6525.37,4318.6 6565.37,4318.6 6605.37,4318.6
VOLTAGE_ADC: FPC1.15 R13.1 | length 1000.5
  Top Layer w8: v1(5064.42,4811.82) R13.1@5064.42,4841.29 ; v1(5886.14,4737.96) FPC1.15@5886.14,4778.4
  Inner1 w8: v1(5064.42,4811.82) 5158.96,4906.36 5429.2,4906.36 5556.1,4779.46 5844.64,4779.46 v1(5886.14,4737.96)
VREF: C52.2 R66.2 R67.1 U5.1 U6.1 U7.1 U8.1 U9.1 U10.1 | length 1707.1
  Top Layer w8: R67.1@5895.98,3905.7 5874.52,3927.16 C52.2@5874.52,4011.66 5874.52,4091.16 R66.2@5895.98,4112.62 5960.94,4112.62 v1(5989.98,4141.66)
  Bottom Layer w8: U8.1@5696.22,4483.16 5659.48,4483.16 ; U7.1@5696.28,4347.11 5659.48,4347.11 ; U5.1@5696.28,4619.34 5670.36,4619.34 5659.48,4608.46 5659.48,4483.16 ; U9.1@6095.68,4432.02 6127.98,4432.02 ; U6.1@6095.68,4568.14 6127.98,4535.84 6127.98,4432.02 ; 5659.48,4347.11 5659.48,4483.16 ; 5659.48,4347.11 5659.48,4269.46 5787.28,4141.66 v1(5989.98,4141.66) 6095.68,4247.36 U10.1@6095.68,4295.91 6112.3,4295.91 6127.98,4311.59 6127.98,4432.02
pads on no net: CN1.3 CN1.4 D1.1 D1.2 D3.1 D3.2 D4.1 D4.2 D5.1 D5.2 FPC1.31 FPC1.32 LED2.1 LED2.2 U1.2 U1.3 U2.6 U13.4 U13.5 U14.4 U14.5

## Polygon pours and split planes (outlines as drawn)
DGND on Bottom Layer (solid, remove dead copper, pour order 6): 5645.98,4764.96 6145.98,4764.96 6145.98,3994.96 5645.98,3994.96
DGND on Inner2 (solid, remove dead copper): 5645.98,4764.96 6145.98,4764.96 6145.98,3994.96 5645.98,3994.96
DGND on Inner1 (solid, remove dead copper): 5645.98,4764.96 6145.98,4764.96 6145.98,3994.96 5645.98,3994.96
DGND on Top Layer (solid, remove dead copper, pour order 0): 5645.98,4764.96 6145.98,4764.96 6145.98,3994.96 5645.98,3994.96
DGND on Bottom Layer (solid, remove dead copper, pour order 8): 5515.98,4963.26 6275.98,4963.26 6275.98,4752.96 5515.98,4752.96
DGND on Inner2 (solid, remove dead copper): 5515.98,4963.26 6275.98,4963.26 6275.98,4752.96 5515.98,4752.96
DGND on Inner1 (solid, remove dead copper): 5515.98,4963.26 6275.98,4963.26 6275.98,4752.96 5515.98,4752.96
DGND on Top Layer (solid, remove dead copper, pour order 2): 5515.98,4963.26 6275.98,4963.26 6275.98,4752.96 5515.98,4752.96
PGND on Inner2 (solid, remove dead copper): 3859.88,5737.26 7893.98,5737.26 7893.98,3306.96 3859.88,3306.96
PGND on Inner1 (solid, remove dead copper): 3859.88,5737.26 7893.98,5737.26 7893.98,3306.96 3859.88,3306.96
PGND on Bottom Layer (solid, remove dead copper, pour order 10): 3859.88,5737.26 7893.98,5737.26 7893.98,3306.96 3859.88,3306.96
PGND on Top Layer (solid, remove dead copper, pour order 4): 3859.88,5737.26 7893.98,5737.26 7893.98,3306.96 3859.88,3306.96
